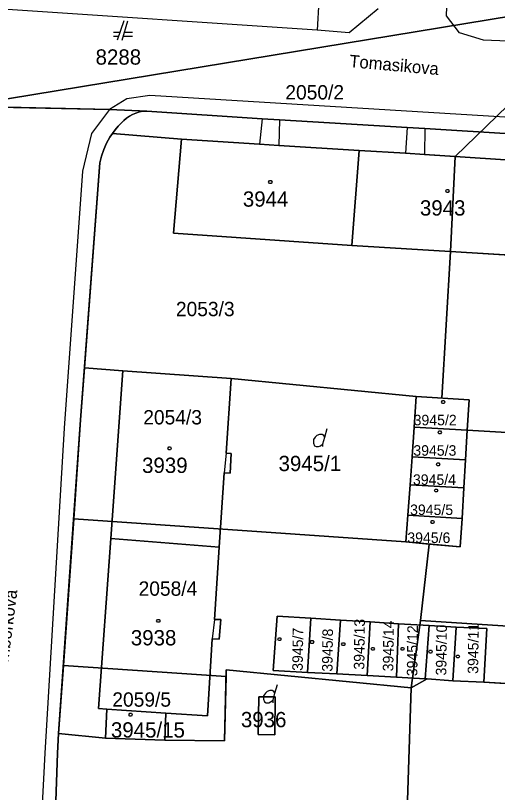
# Model space of a CAD drawing. Extents: x -263587 to -261993, y -1238795 to -1236748.
# Drawn here: x -262927.6 to -262877.2, y -1238000.9 to -1237919.7 of the extents above; entities that cross this region are included whole.
import ezdxf

# ---------------------------------------------------------------- set-up
doc = ezdxf.new("R2010")
doc.units = 0
doc.layers.add('Vrstva 1', color=7, linetype='Continuous')
doc.layers.add('Vrstva 3', color=7, linetype='Continuous')

msp = doc.modelspace()

# ---------------------------------------------------------------- linework, layer by layer
at = {"layer": 'Vrstva 1'}
for p, q in [((-262896.03, -1237921.2), (-262972.45, -1237916.14)), ((-262882.51, -1237919.7), (-262882.4, -1237916.05)), ((-262895.87, -1237918.15), (-262896.03, -1237921.2)), ((-262889.66, -1237918.97), (-262892.68, -1237921.5)), ((-262881.17, -1237921.5), (-262882.51, -1237919.7)), ((-262916.23, -1237920.24), (-262916.93, -1237922.24)), ((-262916.43, -1237922.24), (-262915.83, -1237920.24)), ((-262892.68, -1237921.5), (-262896.03, -1237921.2)), ((-262916.65, -1237921.44), (-262917.33, -1237921.44)), ((-262917.33, -1237921.84), (-262916.79, -1237921.84)), ((-262916.31, -1237921.84), (-262915.33, -1237921.84)), ((-262915.33, -1237921.44), (-262916.19, -1237921.44)), ((-262878.64, -1237922.26), (-262881.17, -1237921.5)), ((-262876.09, -1237922.34), (-262878.64, -1237922.26)), ((-262915.94, -1237928.38), (-262917.75, -1237929.51)), ((-262913.51, -1237928.02), (-262915.94, -1237928.38)), ((-262851.03, -1237931.88), (-262913.51, -1237928.02)), ((-262917.75, -1237929.51), (-262930.07, -1237929.23)), ((-262930.07, -1237929.23), (-262917.75, -1237929.51)), ((-262917.75, -1237929.51), (-262919.63, -1237932.01)), ((-262913.84, -1237929.66), (-262917.75, -1237929.51)), ((-262917.75, -1237929.51), (-262913.84, -1237929.66)), ((-262915.65, -1237930.2), (-262915.96, -1237930.41)), ((-262915.96, -1237930.41), (-262915.65, -1237930.2)), ((-262915.33, -1237930.03), (-262915.65, -1237930.2)), ((-262915.65, -1237930.2), (-262915.33, -1237930.03)), ((-262914.98, -1237929.88), (-262915.33, -1237930.03)), ((-262915.33, -1237930.03), (-262914.98, -1237929.88)), ((-262914.61, -1237929.76), (-262914.98, -1237929.88)), ((-262914.98, -1237929.88), (-262914.61, -1237929.76)), ((-262914.23, -1237929.69), (-262914.61, -1237929.76)), ((-262914.61, -1237929.76), (-262914.23, -1237929.69)), ((-262913.84, -1237929.66), (-262914.23, -1237929.69)), ((-262914.23, -1237929.69), (-262913.84, -1237929.66)), ((-262901.78, -1237930.48), (-262913.84, -1237929.66)), ((-262913.84, -1237929.66), (-262901.78, -1237930.48)), ((-262916.49, -1237930.91), (-262916.83, -1237931.25)), ((-262916.83, -1237931.25), (-262916.49, -1237930.91)), ((-262916.23, -1237930.65), (-262916.49, -1237930.91)), ((-262916.49, -1237930.91), (-262916.23, -1237930.65)), ((-262915.96, -1237930.41), (-262916.23, -1237930.65)), ((-262916.23, -1237930.65), (-262915.96, -1237930.41)), ((-262901.78, -1237930.48), (-262902.07, -1237933.12)), ((-262899.98, -1237930.59), (-262901.78, -1237930.48)), ((-262901.78, -1237930.48), (-262899.98, -1237930.59)), ((-262899.98, -1237930.59), (-262900.04, -1237933.25)), ((-262886.62, -1237931.38), (-262899.98, -1237930.59)), ((-262899.98, -1237930.59), (-262886.62, -1237931.38)), ((-262917.15, -1237931.62), (-262917.44, -1237932)), ((-262917.44, -1237932), (-262917.15, -1237931.62)), ((-262916.83, -1237931.25), (-262917.15, -1237931.62)), ((-262917.15, -1237931.62), (-262916.83, -1237931.25)), ((-262886.62, -1237931.38), (-262886.79, -1237934.08)), ((-262884.79, -1237931.49), (-262886.62, -1237931.38)), ((-262886.62, -1237931.38), (-262884.79, -1237931.49)), ((-262884.79, -1237931.49), (-262884.82, -1237934.21)), ((-262854.37, -1237933.41), (-262884.79, -1237931.49)), ((-262884.79, -1237931.49), (-262854.37, -1237933.41)), ((-262919.63, -1237932.01), (-262920.57, -1237935.96)), ((-262917.71, -1237932.4), (-262918.06, -1237933.03)), ((-262918.06, -1237933.03), (-262917.71, -1237932.4)), ((-262917.44, -1237932), (-262917.71, -1237932.4)), ((-262917.71, -1237932.4), (-262917.44, -1237932)), ((-262911.04, -1237942.44), (-262910.21, -1237932.61)), ((-262910.21, -1237932.61), (-262911.04, -1237942.44)), ((-262910.21, -1237932.61), (-262902.07, -1237933.12)), ((-262902.07, -1237933.12), (-262910.21, -1237932.61)), ((-262918.06, -1237933.03), (-262918.35, -1237933.69)), ((-262918.35, -1237933.69), (-262918.06, -1237933.03)), ((-262902.07, -1237933.12), (-262900.04, -1237933.25)), ((-262900.04, -1237933.25), (-262902.07, -1237933.12)), ((-262900.04, -1237933.25), (-262891.66, -1237933.77)), ((-262891.66, -1237933.77), (-262900.04, -1237933.25)), ((-262918.58, -1237934.38), (-262918.74, -1237935.08)), ((-262918.74, -1237935.08), (-262918.58, -1237934.38)), ((-262918.35, -1237933.69), (-262918.58, -1237934.38)), ((-262918.58, -1237934.38), (-262918.35, -1237933.69)), ((-262892.4, -1237943.72), (-262891.66, -1237933.77)), ((-262891.66, -1237933.77), (-262892.4, -1237943.72)), ((-262891.66, -1237933.77), (-262886.79, -1237934.08)), ((-262886.79, -1237934.08), (-262891.66, -1237933.77)), ((-262886.79, -1237934.08), (-262884.82, -1237934.21)), ((-262884.82, -1237934.21), (-262886.79, -1237934.08)), ((-262884.82, -1237934.21), (-262872.95, -1237934.97)), ((-262872.95, -1237934.97), (-262884.82, -1237934.21)), ((-262918.74, -1237935.08), (-262920.76, -1237961.94)), ((-262920.76, -1237961.94), (-262918.74, -1237935.08)), ((-262920.57, -1237935.96), (-262922.48, -1237962.83)), ((-262892.4, -1237943.72), (-262911.04, -1237942.44)), ((-262911.04, -1237942.44), (-262892.4, -1237943.72)), ((-262873.68, -1237944.86), (-262892.4, -1237943.72)), ((-262892.4, -1237943.72), (-262873.68, -1237944.86)), ((-262917.6, -1237974.35), (-262916.34, -1237956.82)), ((-262916.34, -1237956.82), (-262917.6, -1237974.35)), ((-262916.34, -1237956.82), (-262905.03, -1237957.62)), ((-262905.03, -1237957.62), (-262916.34, -1237956.82)), ((-262905.03, -1237957.62), (-262905.55, -1237965.44)), ((-262905.55, -1237965.44), (-262905.03, -1237957.62)), ((-262885.9, -1237962.71), (-262885.67, -1237959.51)), ((-262885.67, -1237959.51), (-262885.9, -1237962.71)), ((-262885.67, -1237959.51), (-262880.14, -1237959.84)), ((-262880.14, -1237959.84), (-262885.67, -1237959.51)), ((-262880.14, -1237959.84), (-262880.34, -1237963.02)), ((-262880.34, -1237963.02), (-262880.14, -1237959.84)), ((-262920.76, -1237961.94), (-262923.07, -1237994.75)), ((-262923.07, -1237994.75), (-262920.76, -1237961.94)), ((-262886.12, -1237965.81), (-262885.9, -1237962.71)), ((-262885.9, -1237962.71), (-262886.12, -1237965.81)), ((-262885.9, -1237962.71), (-262880.34, -1237963.02)), ((-262880.34, -1237963.02), (-262885.9, -1237962.71)), ((-262922.48, -1237962.83), (-262924.5, -1237996.8)), ((-262895.25, -1237963.75), (-262894.98, -1237962.85)), ((-262880.34, -1237963.02), (-262880.52, -1237966.12)), ((-262880.52, -1237966.12), (-262880.34, -1237963.02)), ((-262905.55, -1237965.44), (-262905.74, -1237967.5)), ((-262905.55, -1237965.44), (-262905.04, -1237965.47)), ((-262905.04, -1237965.47), (-262905.55, -1237965.44)), ((-262905.04, -1237965.47), (-262905.13, -1237967.52)), ((-262905.13, -1237967.52), (-262905.04, -1237965.47)), ((-262886.33, -1237968.76), (-262886.12, -1237965.81)), ((-262886.12, -1237965.81), (-262886.33, -1237968.76)), ((-262886.12, -1237965.81), (-262880.52, -1237966.12)), ((-262880.52, -1237966.12), (-262886.12, -1237965.81)), ((-262880.52, -1237966.12), (-262880.7, -1237969.07)), ((-262880.7, -1237969.07), (-262880.52, -1237966.12)), ((-262905.74, -1237967.5), (-262906.28, -1237975.27)), ((-262906.28, -1237975.27), (-262905.74, -1237967.5)), ((-262905.13, -1237967.52), (-262905.74, -1237967.5)), ((-262905.74, -1237967.5), (-262905.13, -1237967.52)), ((-262886.56, -1237971.93), (-262886.33, -1237968.76)), ((-262886.33, -1237968.76), (-262886.56, -1237971.93)), ((-262880.7, -1237969.07), (-262886.33, -1237968.76)), ((-262886.33, -1237968.76), (-262880.7, -1237969.07)), ((-262880.7, -1237969.07), (-262880.89, -1237972.25)), ((-262880.89, -1237972.25), (-262880.7, -1237969.07)), ((-262886.75, -1237974.72), (-262886.56, -1237971.93)), ((-262886.56, -1237971.93), (-262886.75, -1237974.72)), ((-262880.89, -1237972.25), (-262886.56, -1237971.93)), ((-262886.56, -1237971.93), (-262880.89, -1237972.25)), ((-262880.89, -1237972.25), (-262881.07, -1237975.22)), ((-262881.07, -1237975.22), (-262880.89, -1237972.25)), ((-262918.91, -1237992.13), (-262917.6, -1237974.35)), ((-262917.6, -1237974.35), (-262918.91, -1237992.13)), ((-262906.28, -1237975.27), (-262917.6, -1237974.35)), ((-262917.6, -1237974.35), (-262906.28, -1237975.27)), ((-262881.07, -1237975.22), (-262886.75, -1237974.72)), ((-262886.75, -1237974.72), (-262881.07, -1237975.22)), ((-262906.28, -1237975.27), (-262906.77, -1237982.81)), ((-262906.77, -1237982.81), (-262906.28, -1237975.27)), ((-262906.77, -1237982.81), (-262907, -1237984.83)), ((-262906.77, -1237982.81), (-262906.12, -1237982.84)), ((-262906.12, -1237982.84), (-262906.77, -1237982.81)), ((-262906.12, -1237982.84), (-262906.27, -1237984.87)), ((-262906.27, -1237984.87), (-262906.12, -1237982.84)), ((-262900.63, -1237988.17), (-262900.2, -1237982.48)), ((-262900.2, -1237982.48), (-262900.63, -1237988.17)), ((-262900.2, -1237982.48), (-262896.71, -1237982.69)), ((-262896.71, -1237982.69), (-262900.2, -1237982.48)), ((-262897.06, -1237988.36), (-262896.71, -1237982.69)), ((-262896.71, -1237982.69), (-262897.06, -1237988.36)), ((-262896.71, -1237982.69), (-262893.6, -1237982.89)), ((-262893.6, -1237982.89), (-262896.71, -1237982.69)), ((-262893.97, -1237988.52), (-262893.6, -1237982.89)), ((-262893.6, -1237982.89), (-262893.97, -1237988.52)), ((-262893.6, -1237982.89), (-262890.49, -1237983.08)), ((-262890.49, -1237983.08), (-262893.6, -1237982.89)), ((-262890.81, -1237988.69), (-262890.49, -1237983.08)), ((-262890.49, -1237983.08), (-262890.81, -1237988.69)), ((-262890.49, -1237983.08), (-262887.54, -1237983.26)), ((-262887.54, -1237983.26), (-262890.49, -1237983.08)), ((-262887.75, -1237988.86), (-262887.54, -1237983.26)), ((-262887.54, -1237983.26), (-262887.75, -1237988.86)), ((-262887.54, -1237983.26), (-262884.32, -1237983.46)), ((-262884.32, -1237983.46), (-262887.54, -1237983.26)), ((-262884.75, -1237989.02), (-262884.32, -1237983.46)), ((-262884.32, -1237983.46), (-262884.75, -1237989.02)), ((-262884.32, -1237983.46), (-262881.52, -1237983.64)), ((-262881.52, -1237983.64), (-262884.32, -1237983.46)), ((-262881.52, -1237983.64), (-262881.84, -1237989.22)), ((-262881.84, -1237989.22), (-262881.52, -1237983.64)), ((-262881.52, -1237983.64), (-262878.31, -1237983.75)), ((-262878.31, -1237983.75), (-262881.52, -1237983.64)), ((-262878.31, -1237983.75), (-262878.62, -1237989.39)), ((-262878.62, -1237989.39), (-262878.31, -1237983.75)), ((-262907, -1237984.83), (-262907.5, -1237992.9)), ((-262907.5, -1237992.9), (-262907, -1237984.83)), ((-262906.27, -1237984.87), (-262907, -1237984.83)), ((-262907, -1237984.83), (-262906.27, -1237984.87)), ((-262905.72, -1237995.52), (-262905.54, -1237988.07)), ((-262905.54, -1237988.07), (-262905.72, -1237995.52)), ((-262905.54, -1237988.07), (-262886.21, -1237989.97)), ((-262886.21, -1237989.97), (-262905.54, -1237988.07)), ((-262897.06, -1237988.36), (-262900.63, -1237988.17)), ((-262900.63, -1237988.17), (-262897.06, -1237988.36)), ((-262893.97, -1237988.52), (-262897.06, -1237988.36)), ((-262897.06, -1237988.36), (-262893.97, -1237988.52)), ((-262890.81, -1237988.69), (-262893.97, -1237988.52)), ((-262893.97, -1237988.52), (-262890.81, -1237988.69)), ((-262887.75, -1237988.86), (-262890.81, -1237988.69)), ((-262890.81, -1237988.69), (-262887.75, -1237988.86)), ((-262900.46, -1237990.53), (-262900.19, -1237989.63)), ((-262884.75, -1237989.02), (-262887.75, -1237988.86)), ((-262887.75, -1237988.86), (-262884.75, -1237989.02)), ((-262886.21, -1237989.97), (-262884.52, -1237989.02)), ((-262884.52, -1237989.02), (-262886.21, -1237989.97)), ((-262884.52, -1237989.02), (-262884.75, -1237989.02)), ((-262884.75, -1237989.02), (-262884.52, -1237989.02)), ((-262884.52, -1237989.02), (-262881.84, -1237989.22)), ((-262881.84, -1237989.22), (-262884.52, -1237989.02)), ((-262881.84, -1237989.22), (-262878.62, -1237989.39)), ((-262878.62, -1237989.39), (-262881.84, -1237989.22)), ((-262878.62, -1237989.39), (-262860.25, -1237990.46)), ((-262860.25, -1237990.46), (-262878.62, -1237989.39)), ((-262886.65, -1238002.99), (-262886.21, -1237989.97)), ((-262886.21, -1237989.97), (-262886.65, -1238002.99)), ((-262902.12, -1237990.91), (-262902.2, -1237994.86)), ((-262902.2, -1237994.86), (-262902.12, -1237990.91)), ((-262900.41, -1237990.91), (-262902.12, -1237990.91)), ((-262902.12, -1237990.91), (-262900.41, -1237990.91)), ((-262900.47, -1237994.88), (-262900.41, -1237990.91)), ((-262900.41, -1237990.91), (-262900.47, -1237994.88)), ((-262918.02, -1237992.19), (-262918.91, -1237992.13)), ((-262918.91, -1237992.13), (-262918.02, -1237992.19)), ((-262918.17, -1237995.24), (-262918.02, -1237992.19)), ((-262918.02, -1237992.19), (-262918.17, -1237995.24)), ((-262911.85, -1237992.61), (-262918.02, -1237992.19)), ((-262918.02, -1237992.19), (-262911.85, -1237992.61)), ((-262911.85, -1237992.61), (-262911.95, -1237995.44)), ((-262911.95, -1237995.44), (-262911.85, -1237992.61)), ((-262907.5, -1237992.9), (-262911.85, -1237992.61)), ((-262911.85, -1237992.61), (-262907.5, -1237992.9)), ((-262923.07, -1237994.75), (-262923.19, -1237996.8)), ((-262923.19, -1237996.8), (-262923.07, -1237994.75)), ((-262923.07, -1237994.75), (-262918.17, -1237995.24)), ((-262918.17, -1237995.24), (-262923.07, -1237994.75)), ((-262911.95, -1237995.44), (-262918.17, -1237995.24)), ((-262918.17, -1237995.24), (-262911.95, -1237995.44)), ((-262902.2, -1237994.86), (-262900.47, -1237994.88)), ((-262900.47, -1237994.88), (-262902.2, -1237994.86)), ((-262911.95, -1237995.44), (-262905.72, -1237995.52)), ((-262905.72, -1237995.52), (-262911.95, -1237995.44)), ((-262924.5, -1237996.8), (-262925.57, -1238016.17)), ((-262923.19, -1237996.8), (-262923.88, -1238016.37)), ((-262923.88, -1238016.37), (-262923.19, -1237996.8))]:
    msp.add_line(p, q, dxfattribs=at)
for points in [[(-262900.84, -1237936.94), (-262900.75, -1237937.09), (-262900.84, -1237937.24), (-262901.02, -1237937.24), (-262901.11, -1237937.09), (-262901.02, -1237936.94)], [(-262882.33, -1237937.87), (-262882.24, -1237938.02), (-262882.33, -1237938.17), (-262882.51, -1237938.17), (-262882.6, -1237938.02), (-262882.51, -1237937.87)], [(-262882.77, -1237959.94), (-262882.68, -1237960.09), (-262882.77, -1237960.24), (-262882.95, -1237960.24), (-262883.04, -1237960.09), (-262882.95, -1237959.94)], [(-262883.13, -1237963.11), (-262883.04, -1237963.26), (-262883.13, -1237963.41), (-262883.31, -1237963.41), (-262883.4, -1237963.26), (-262883.31, -1237963.11)], [(-262911.37, -1237964.78), (-262911.28, -1237964.93), (-262911.37, -1237965.08), (-262911.55, -1237965.08), (-262911.64, -1237964.93), (-262911.55, -1237964.78)], [(-262883.3, -1237966.45), (-262883.21, -1237966.6), (-262883.3, -1237966.75), (-262883.48, -1237966.75), (-262883.57, -1237966.6), (-262883.48, -1237966.45)], [(-262883.51, -1237969.19), (-262883.42, -1237969.34), (-262883.51, -1237969.49), (-262883.69, -1237969.49), (-262883.78, -1237969.34), (-262883.69, -1237969.19)], [(-262883.88, -1237972.47), (-262883.79, -1237972.62), (-262883.88, -1237972.77), (-262884.06, -1237972.77), (-262884.15, -1237972.62), (-262884.06, -1237972.47)], [(-262912.55, -1237982.81), (-262912.46, -1237982.96), (-262912.55, -1237983.11), (-262912.73, -1237983.11), (-262912.82, -1237982.96), (-262912.73, -1237982.81)], [(-262899.89, -1237984.73), (-262899.8, -1237984.88), (-262899.89, -1237985.03), (-262900.07, -1237985.03), (-262900.16, -1237984.88), (-262900.07, -1237984.73)], [(-262896.48, -1237985.03), (-262896.39, -1237985.18), (-262896.48, -1237985.33), (-262896.66, -1237985.33), (-262896.75, -1237985.18), (-262896.66, -1237985.03)], [(-262893.21, -1237985.25), (-262893.12, -1237985.4), (-262893.21, -1237985.55), (-262893.39, -1237985.55), (-262893.48, -1237985.4), (-262893.39, -1237985.25)], [(-262890.13, -1237985.74), (-262890.04, -1237985.89), (-262890.13, -1237986.04), (-262890.31, -1237986.04), (-262890.4, -1237985.89), (-262890.31, -1237985.74)], [(-262887.02, -1237985.74), (-262886.93, -1237985.89), (-262887.02, -1237986.04), (-262887.2, -1237986.04), (-262887.29, -1237985.89), (-262887.2, -1237985.74)], [(-262884.1, -1237986.04), (-262884.01, -1237986.19), (-262884.1, -1237986.34), (-262884.28, -1237986.34), (-262884.37, -1237986.19), (-262884.28, -1237986.04)], [(-262881.24, -1237986.54), (-262881.15, -1237986.69), (-262881.24, -1237986.84), (-262881.42, -1237986.84), (-262881.51, -1237986.69), (-262881.42, -1237986.54)], [(-262915.45, -1237992.63), (-262915.36, -1237992.78), (-262915.45, -1237992.93), (-262915.63, -1237992.93), (-262915.72, -1237992.78), (-262915.63, -1237992.63)]]:
    msp.add_lwpolyline(points, close=True, dxfattribs=at)
for points in [[(-262895.43, -1237964.74), (-262895.43, -1237964.47), (-262895.25, -1237963.75), (-262895.34, -1237963.57), (-262895.52, -1237963.48), (-262895.79, -1237963.48), (-262896.06, -1237963.57), (-262896.24, -1237963.75), (-262896.42, -1237964.02), (-262896.42, -1237964.38), (-262896.33, -1237964.65), (-262896.15, -1237964.74), (-262895.88, -1237964.74), (-262895.7, -1237964.65), (-262895.43, -1237964.47)], [(-262900.64, -1237991.52), (-262900.64, -1237991.25), (-262900.46, -1237990.53), (-262900.55, -1237990.35), (-262900.73, -1237990.26), (-262901, -1237990.26), (-262901.27, -1237990.35), (-262901.45, -1237990.53), (-262901.63, -1237990.8), (-262901.63, -1237991.16), (-262901.54, -1237991.43), (-262901.36, -1237991.52), (-262901.09, -1237991.52), (-262900.91, -1237991.43), (-262900.64, -1237991.25)]]:
    msp.add_lwpolyline(points, dxfattribs=at)
at = {"layer": 'Vrstva 3'}
for points in [[(-262860.57, -1237917.21), (-262933.33, -1237929.2), (-263003.431, -1237940.93), (-263002.45, -1237923.11), (-262999.65, -1237922.63), (-262998.06, -1237922.69), (-262998.41, -1237914.79), (-262998.53, -1237912.83), (-262978.63, -1237913.8), (-262892, -1237918.78), (-262891.61, -1237915.41), (-262889.11, -1237915.59), (-262882.4, -1237916.05), (-262878.86, -1237916.29), (-262866.76, -1237916.95)], [(-262847.58, -1237946.48), (-262856.91, -1237946.09), (-262873.68, -1237944.86), (-262882.09, -1237944.35), (-262881.62, -1237934.41), (-262869.54, -1237922.73), (-262849.01, -1237923.97), (-262845.99, -1237924.31), (-262846.6, -1237933.73), (-262846.92, -1237937.53), (-262847.43, -1237944.68)], [(-262881.62, -1237934.41), (-262882.09, -1237944.35), (-262883, -1237959.669), (-262885.67, -1237959.51), (-262905.03, -1237957.62), (-262916.34, -1237956.82), (-262920.35, -1237956.5), (-262918.74, -1237935.08), (-262918.58, -1237934.38), (-262918.35, -1237933.69), (-262918.06, -1237933.03), (-262917.71, -1237932.4), (-262917.44, -1237932), (-262910.21, -1237932.61), (-262902.07, -1237933.12), (-262900.04, -1237933.25), (-262891.66, -1237933.77), (-262886.79, -1237934.08), (-262884.82, -1237934.21)], [(-262848.856, -1237964.86), (-262880.34, -1237963.02), (-262880.14, -1237959.84), (-262883, -1237959.669), (-262882.09, -1237944.35), (-262873.68, -1237944.86), (-262856.91, -1237946.09), (-262847.58, -1237946.48), (-262848.55, -1237959.8), (-262848.67, -1237962.18)], [(-262885.67, -1237959.51), (-262885.9, -1237962.71), (-262886.12, -1237965.81), (-262886.33, -1237968.76), (-262886.56, -1237971.93), (-262886.75, -1237974.72), (-262921.489, -1237972.29), (-262920.76, -1237961.94), (-262920.35, -1237956.5), (-262916.34, -1237956.82), (-262905.03, -1237957.62)], [(-262850.265, -1237985.19), (-262885.24, -1237982.92), (-262884.33, -1237974.933), (-262881.07, -1237975.22), (-262880.89, -1237972.25), (-262880.7, -1237969.07), (-262880.52, -1237966.12), (-262880.34, -1237963.02), (-262848.856, -1237964.86), (-262849.77, -1237978), (-262849.89, -1237980.07)], [(-262886.75, -1237974.72), (-262884.33, -1237974.933), (-262885.24, -1237982.92), (-262885.29, -1237983.4), (-262886.21, -1237989.97), (-262905.54, -1237988.07), (-262905.558, -1237988.8), (-262922.569, -1237987.63), (-262921.489, -1237972.29)], [(-262885.24, -1237982.92), (-262850.265, -1237985.19), (-262850.71, -1237991.26), (-262860.25, -1237990.46), (-262878.62, -1237989.39), (-262881.84, -1237989.22), (-262881.52, -1237983.64), (-262884.32, -1237983.46), (-262884.75, -1237989.02), (-262884.52, -1237989.02), (-262886.21, -1237989.97), (-262885.29, -1237983.4)], [(-262922.569, -1237987.63), (-262905.558, -1237988.8), (-262905.72, -1237995.52), (-262911.95, -1237995.44), (-262918.17, -1237995.24), (-262923.07, -1237994.75)]]:
    msp.add_lwpolyline(points, close=True, dxfattribs=at)
for points in [[(-262933.33, -1237929.2), (-262860.57, -1237917.21)], [(-262869.54, -1237922.73), (-262881.62, -1237934.41), (-262884.82, -1237934.21), (-262886.79, -1237934.08), (-262891.66, -1237933.77), (-262900.04, -1237933.25), (-262902.07, -1237933.12), (-262910.21, -1237932.61), (-262917.44, -1237932), (-262917.15, -1237931.62), (-262916.83, -1237931.25), (-262916.49, -1237930.91), (-262916.23, -1237930.65), (-262915.96, -1237930.41), (-262915.65, -1237930.2), (-262915.33, -1237930.03), (-262914.98, -1237929.88), (-262914.61, -1237929.76), (-262914.23, -1237929.69), (-262913.84, -1237929.66), (-262917.75, -1237929.51), (-262930.07, -1237929.23)], [(-262930.07, -1237929.23), (-262917.75, -1237929.51), (-262913.84, -1237929.66), (-262914.23, -1237929.69), (-262914.61, -1237929.76), (-262914.98, -1237929.88), (-262915.33, -1237930.03), (-262915.65, -1237930.2), (-262915.96, -1237930.41), (-262916.23, -1237930.65), (-262916.49, -1237930.91), (-262916.83, -1237931.25), (-262917.15, -1237931.62), (-262917.44, -1237932), (-262917.71, -1237932.4), (-262918.06, -1237933.03), (-262918.35, -1237933.69), (-262918.58, -1237934.38), (-262918.74, -1237935.08), (-262920.35, -1237956.5), (-262920.76, -1237961.94), (-262921.489, -1237972.29), (-262922.569, -1237987.63), (-262923.07, -1237994.75), (-262918.17, -1237995.24), (-262911.95, -1237995.44), (-262905.72, -1237995.52), (-262905.558, -1237988.8), (-262905.54, -1237988.07), (-262886.21, -1237989.97), (-262884.52, -1237989.02), (-262884.75, -1237989.02), (-262884.32, -1237983.46), (-262881.52, -1237983.64), (-262881.84, -1237989.22), (-262878.62, -1237989.39), (-262860.25, -1237990.46)]]:
    msp.add_lwpolyline(points, dxfattribs=at)

# ---------------------------------------------------------------- texts
at = {"layer": 'Vrstva 1'}
for s, height, p in [('8288', 1.6, (-262919.198, -1237924.81)), ('3944', 1.6, (-262903.804, -1237939.66)), ('3943', 1.6, (-262885.294, -1237940.59)), ('3945/2', 1.1, (-262885.952, -1237962.52)), ('3945/3', 1.1, (-262885.982, -1237965.7)), ('3939', 1.6, (-262914.34, -1237967.5)), ('3945/1', 1.6, (-262900.07, -1237967.31)), ('3945/4', 1.1, (-262886.022, -1237968.75)), ('3945/5', 1.1, (-262886.322, -1237971.9)), ('3945/6', 1.1, (-262886.612, -1237974.82)), ('3938', 1.6, (-262915.514, -1237985.53)), ('3936', 1.6, (-262904.008, -1237994.09)), ('3945/15', 1.6, (-262917.594, -1237995.17))]:
    msp.add_text(s, height=height, dxfattribs=at).set_placement(p)
for s, height, rotation, p in [('Tomasikova', 1.3, 354.89006, (-262892.715, -1237925.064)), ('Cimborkova', 1.3, 82.73511, (-262928.535, -1237988.978)), ('3945/13', 1.1, 89.32412, (-262891.106, -1237988.077)), ('3945/14', 1.1, 89.32412, (-262888.076, -1237988.247)), ('3945/7', 1.1, 89.32412, (-262897.543, -1237988.195)), ('3945/8', 1.1, 89.32412, (-262894.433, -1237988.285)), ('3945/12', 1.1, 89.32412, (-262885.566, -1237988.757)), ('3945/10', 1.1, 89.32412, (-262882.536, -1237988.684)), ('3945/11', 1.1, 89.32412, (-262879.204, -1237988.507))]:
    msp.add_text(s, height=height, rotation=rotation, dxfattribs=at).set_placement(p)
at = {"layer": 'Vrstva 3'}
for s, p in [('2050/2', (-262899.361, -1237928.45)), ('2053/3', (-262910.801, -1237951.11)), ('2054/3', (-262914.214, -1237962.428)), ('2058/4', (-262914.701, -1237980.34)), ('2059/5', (-262917.446, -1237991.94))]:
    msp.add_text(s, height=1.5, dxfattribs=at).set_placement(p)

doc.saveas('drawing.dxf')
